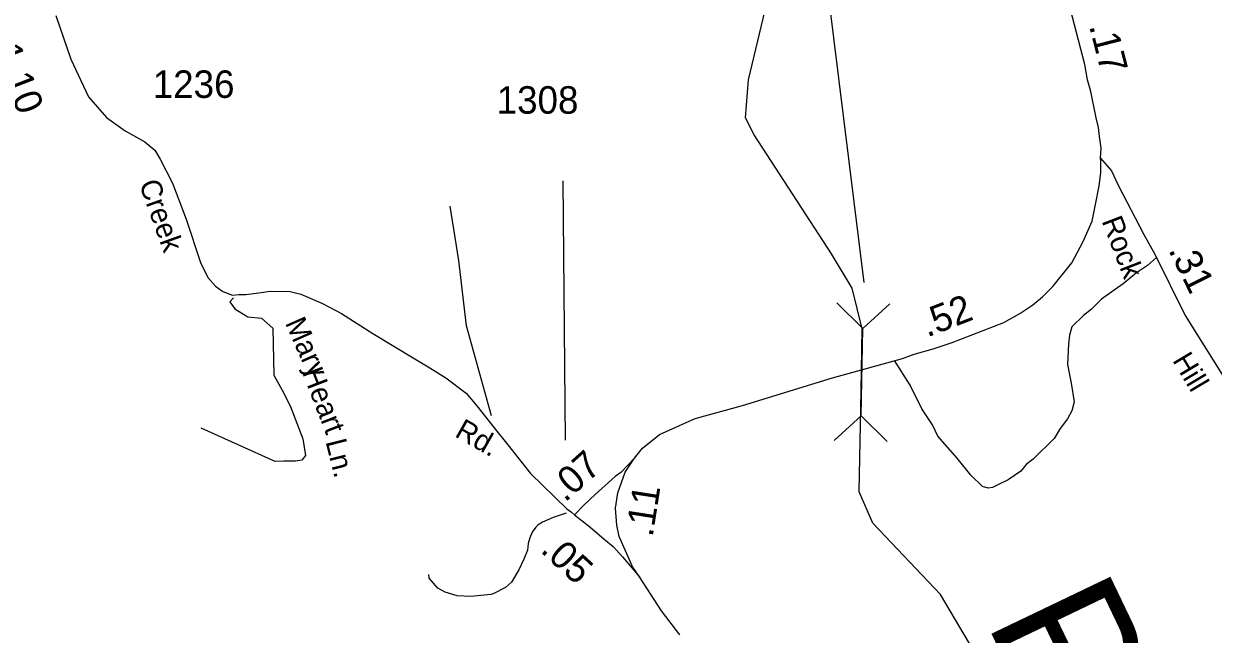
# Model space of a CAD drawing. Extents: x 1113032 to 1302912, y 664689 to 832535.
# Drawn here: x 1134389 to 1139798, y 745173 to 747949 of the extents above; entities that cross this region are included whole.
import ezdxf

# ---------------------------------------------------------------- set-up
doc = ezdxf.new("R2010")
doc.units = 0
for name, color, linetype in [('Exist Hydrographic Creek Single Shore', 7, 'Continuous'), ('Exist Hydrographic Creek Single Shore Label', 7, 'Continuous'), ('Exist Road Non-System Type 51', 7, 'Continuous'), ('Exist Road Non-System Type 51 Label', 7, 'Continuous'), ('Exist Road Primary NC Attributed', 7, 'Continuous'), ('Exist Road Primary NC Service Mileage Hundredths English Label', 7, 'Continuous'), ('Exist Road Primary NC Structure Pipe Attributed CELL', 7, 'Continuous'), ('Exist Road Primary NC Structure Pipe Number Label', 7, 'Continuous'), ('Exist Road Secondary Mileage Hundredths English Label', 7, 'Continuous'), ('Exist Road Secondary Type 51 Attributed', 7, 'Continuous'), ('Exist Road Secondary Type 51 Label', 7, 'Continuous'), ('Exist Road Secondary Type 51 Number Label', 7, 'Continuous')]:
    doc.layers.add(name, color=color, linetype=linetype)

msp = doc.modelspace()

# ---------------------------------------------------------------- linework, layer by layer
at = {"layer": 'Exist Hydrographic Creek Single Shore'}
for points in [[(1138196.4, 746280.4), (1138201.8, 746562), (1138156.8, 746746.7), (1138061.8, 746902.9), (1137710.8, 747445), (1137670.8, 747521.3), (1137684.7, 747694.9), (1137760.7, 748011.9), (1137751.8, 748277.9), (1137701.8, 748564.4), (1137641.8, 748772.4), (1137476.7, 749126.9), (1137371.7, 749506.5), (1137315.7, 749875.3), (1137227.7, 750018.1), (1136846.7, 750081.6), (1136428.7, 750352.5), (1136172.7, 750410.2), (1135803.7, 750637.5), (1135550.7, 750819.8), (1135202.7, 751171.4), (1134785.2, 751787.5)], [(1139750.9, 742280.4), (1139600.9, 742562.4), (1139455.9, 742739.2), (1139126.9, 742893.6), (1138849.9, 743125.6), (1138869.9, 743207.3), (1138930.9, 743298), (1138989.9, 743323), (1139041.9, 743404), (1139089.9, 743626.3), (1138874.9, 744516.8), (1138708.9, 745097.8), (1138557.8, 745353.6), (1138250.8, 745678.1), (1138187.8, 745820.5), (1138196.4, 746280.4)]]:
    msp.add_lwpolyline(points, dxfattribs=at)
at = {"layer": 'Exist Road Non-System Type 51'}
for points in [[(1136516.4, 746166.5), (1136402.5, 746576.4), (1136367.2, 746873.5), (1136327.6, 747120.3)], [(1139539.5, 746886.9), (1139498.6, 746850.8), (1139449.6, 746816.4), (1139388.2, 746766.1), (1139290, 746697.1), (1139242.5, 746650.5), (1139207.8, 746623.3), (1139154.3, 746570.9), (1139145, 746533.3), (1139139.9, 746493.4), (1139135.1, 746399.2), (1139152.7, 746314.9), (1139166.1, 746230.2), (1139154.8, 746188.8), (1139135.7, 746153.1), (1139102.6, 746108.1), (1139075.2, 746063), (1138978.4, 745969.8), (1138947.4, 745944.5), (1138922.5, 745915.4), (1138865.6, 745874.9), (1138818.9, 745852.2), (1138794.4, 745841.2), (1138774.3, 745837.6), (1138748.5, 745844.4), (1138696, 745896), (1138634.2, 745974), (1138545, 746074.6), (1138520.7, 746125.3), (1138472.6, 746198.8), (1138420, 746306.6), (1138348.2, 746418.1)], [(1135342.4, 746702.6), (1135325.9, 746684.4), (1135348.6, 746653), (1135407.9, 746616.3), (1135470.7, 746611.1), (1135521.3, 746565.7), (1135525.5, 746351.3), (1135571.9, 746269), (1135603.3, 746204.4), (1135657.3, 746061.6), (1135669.5, 745986.6), (1135653.1, 745965.4), (1135624.2, 745960.4), (1135570.1, 745960.4), (1135532.6, 745958.4), (1135195.1, 746110.5)], [(1136855.5, 745724.4), (1136797, 745703.9), (1136748.3, 745683.5), (1136728, 745670.2), (1136717.6, 745660.2), (1136701.1, 745636.9), (1136690.1, 745611.2), (1136683.3, 745585.4), (1136680.4, 745555.2), (1136663.2, 745513.9), (1136639.9, 745466.4), (1136606.3, 745409.4), (1136579.5, 745386.3), (1136526.5, 745357.8), (1136512.6, 745354.1), (1136422.1, 745344.8), (1136360.2, 745348.6), (1136304.7, 745364.2), (1136271.3, 745383.2), (1136232.5, 745428.6), (1136230.8, 745444.4)]]:
    msp.add_lwpolyline(points, dxfattribs=at)
at = {"layer": 'Exist Road Primary NC Attributed'}
for points in [[(1139286.1, 747337.7), (1139288.8, 747383.4), (1139280.7, 747436.3), (1139276.2, 747477.5), (1139265.5, 747522.3), (1139241.3, 747641.1), (1139226.1, 747693.9), (1139213.6, 747764.1), (1139129.4, 748091.4), (1139125.9, 748131.7), (1139116.8, 748189), (1139116.9, 748219.5)], [(1137165.7, 745974.2), (1137202.5, 746019), (1137280.4, 746080.8), (1137442.7, 746153.9), (1137656.7, 746214), (1138066.2, 746339.2), (1138384.5, 746426.8), (1138437.4, 746447.4), (1138524.2, 746471.6), (1138611.1, 746499.4), (1138846.2, 746590.3), (1138918.7, 746631.5), (1138977.3, 746671.5), (1139021.2, 746707.3), (1139068.6, 746754.8), (1139154.6, 746862.3), (1139204.6, 746956.9), (1139246.7, 747051), (1139262.9, 747127), (1139278.9, 747211.6), (1139287, 747270.8), (1139287, 747301), (1139287, 747324.3), (1139286.1, 747337.7)], [(1137188.9, 745433.8), (1137158.9, 745478.3), (1137154.1, 745487.6), (1137095.9, 745618), (1137085.2, 745669.1), (1137079.8, 745747.1), (1137090.5, 745816), (1137123.7, 745909.7), (1137165.7, 745974.2)], [(1137372.8, 745170.3), (1137288.7, 745279.2), (1137188.9, 745433.8)]]:
    msp.add_lwpolyline(points, dxfattribs=at)
at = {"layer": 'Exist Road Primary NC Structure Pipe Attributed CELL'}
for p, q in [((1138086.2, 746680.7), (1138204.7, 746563.7)), ((1138328, 746675.7), (1138204.7, 746563.7)), ((1138196.7, 746167), (1138204.7, 746563.7)), ((1138073.5, 746055), (1138196.7, 746167)), ((1138315.3, 746050), (1138196.7, 746167))]:
    msp.add_line(p, q, dxfattribs=at)
at = {"layer": 'Exist Road Primary NC Structure Pipe Number Label'}
msp.add_line((1138210.1, 746773.3), (1138012.7, 748371.9), dxfattribs=at)
at = {"layer": 'Exist Road Secondary Type 51 Attributed'}
for points in [[(1134534.2, 747986.2), (1134603.4, 747787.7), (1134682.7, 747617.1), (1134765.3, 747523.6), (1134850.6, 747461.9), (1134940.1, 747413), (1134985.1, 747374.7), (1135009.4, 747334.3), (1135064.8, 747224.2), (1135111.6, 747104.6), (1135127.3, 747061.4), (1135192.6, 746864), (1135226.6, 746796), (1135260.5, 746756.7), (1135294.3, 746731.9), (1135337.9, 746715.7), (1135367, 746718.2), (1135398.6, 746718.2), (1135457.6, 746725.1), (1135509.7, 746732.8), (1135601.2, 746731.9), (1135648.8, 746720.1), (1135747.1, 746677.3), (1135834.3, 746631.1), (1135976.9, 746540.6), (1136159.7, 746430.2), (1136235.6, 746384.2), (1136308.3, 746339.7), (1136401.2, 746268.9), (1136449.9, 746212.4), (1136488.2, 746161.3), (1136528.4, 746112.5), (1136590, 746033.8), (1136693.3, 745904.9), (1136859, 745743.9), (1136880.2, 745727.6), (1136893.2, 745716.5)], [(1139286.1, 747337.7), (1139335.7, 747280.3), (1139365.2, 747216.1), (1139482.3, 746991.2), (1139532.3, 746901.5), (1139670.4, 746623.1), (1139929.4, 746208.9), (1139963.1, 746118.2), (1139985.5, 746016.2), (1139994.6, 745881.6)], [(1137165.7, 745974.2), (1137104.2, 745908.7), (1137077.7, 745889.9), (1136987.2, 745808.9), (1136936.8, 745761), (1136893.2, 745716.5)], [(1136893.2, 745716.5), (1136963.3, 745660.9), (1137028.3, 745605.3), (1137069.3, 745571.9), (1137111.2, 745524.9), (1137188.9, 745433.8)]]:
    msp.add_lwpolyline(points, dxfattribs=at)
at = {"layer": 'Exist Road Secondary Type 51 Number Label'}
msp.add_line((1136852, 746055.7), (1136841.4, 747235.1), dxfattribs=at)

# ---------------------------------------------------------------- texts
at = {"layer": 'Exist Hydrographic Creek Single Shore Label'}
msp.add_text('Paddy', height=600, rotation=295.6173, dxfattribs=at).set_placement((1138760.9, 745234.9))
at = {"layer": 'Exist Road Non-System Type 51 Label'}
for s, rotation, p in [('Mary', 293.8239, (1135576.1, 746589.1)), ('Heart', 291.0958, (1135653.6, 746365.6)), ('Ln.', 284.1081, (1135760.8, 746049.4))]:
    msp.add_text(s, height=95, rotation=rotation, dxfattribs=at).set_placement(p)
at = {"layer": 'Exist Road Primary NC Service Mileage Hundredths English Label'}
for s, rotation, p in [('.17', 284.4153, (1139233, 747939.6)), ('.52', 21.1453, (1138497.1, 746522.3)), ('.11', 81.1469, (1137248.6, 745612.4))]:
    msp.add_text(s, height=125, rotation=rotation, dxfattribs=at).set_placement(p)
at = {"layer": 'Exist Road Secondary Mileage Hundredths English Label'}
for s, rotation, p in [('1.10', 291.0518, (1134250.4, 747832.3)), ('.31', 296.3824, (1139592.3, 746921.1)), ('.07', 41.8167, (1136850.3, 745770.3)), ('.05', 317.1837, (1136734.1, 745550.5))]:
    msp.add_text(s, height=125, rotation=rotation, dxfattribs=at).set_placement(p)
at = {"layer": 'Exist Road Secondary Type 51 Label'}
for s, rotation, p in [('Creek', 289.8285, (1134911.9, 747221.9)), ('Rock', 291.1052, (1139289.7, 747052.7)), ('Hill', 300.9343, (1139610.1, 746418.9)), ('Rd.', 330.4274, (1136344.2, 746074.7))]:
    msp.add_text(s, height=95, rotation=rotation, dxfattribs=at).set_placement(p)
at = {"layer": 'Exist Road Secondary Type 51 Number Label'}
for s, p in [('1236', (1134975.5, 747612.2)), ('1308', (1136539.5, 747540.4))]:
    msp.add_text(s, height=125, dxfattribs=at).set_placement(p)

doc.saveas('drawing.dxf')
